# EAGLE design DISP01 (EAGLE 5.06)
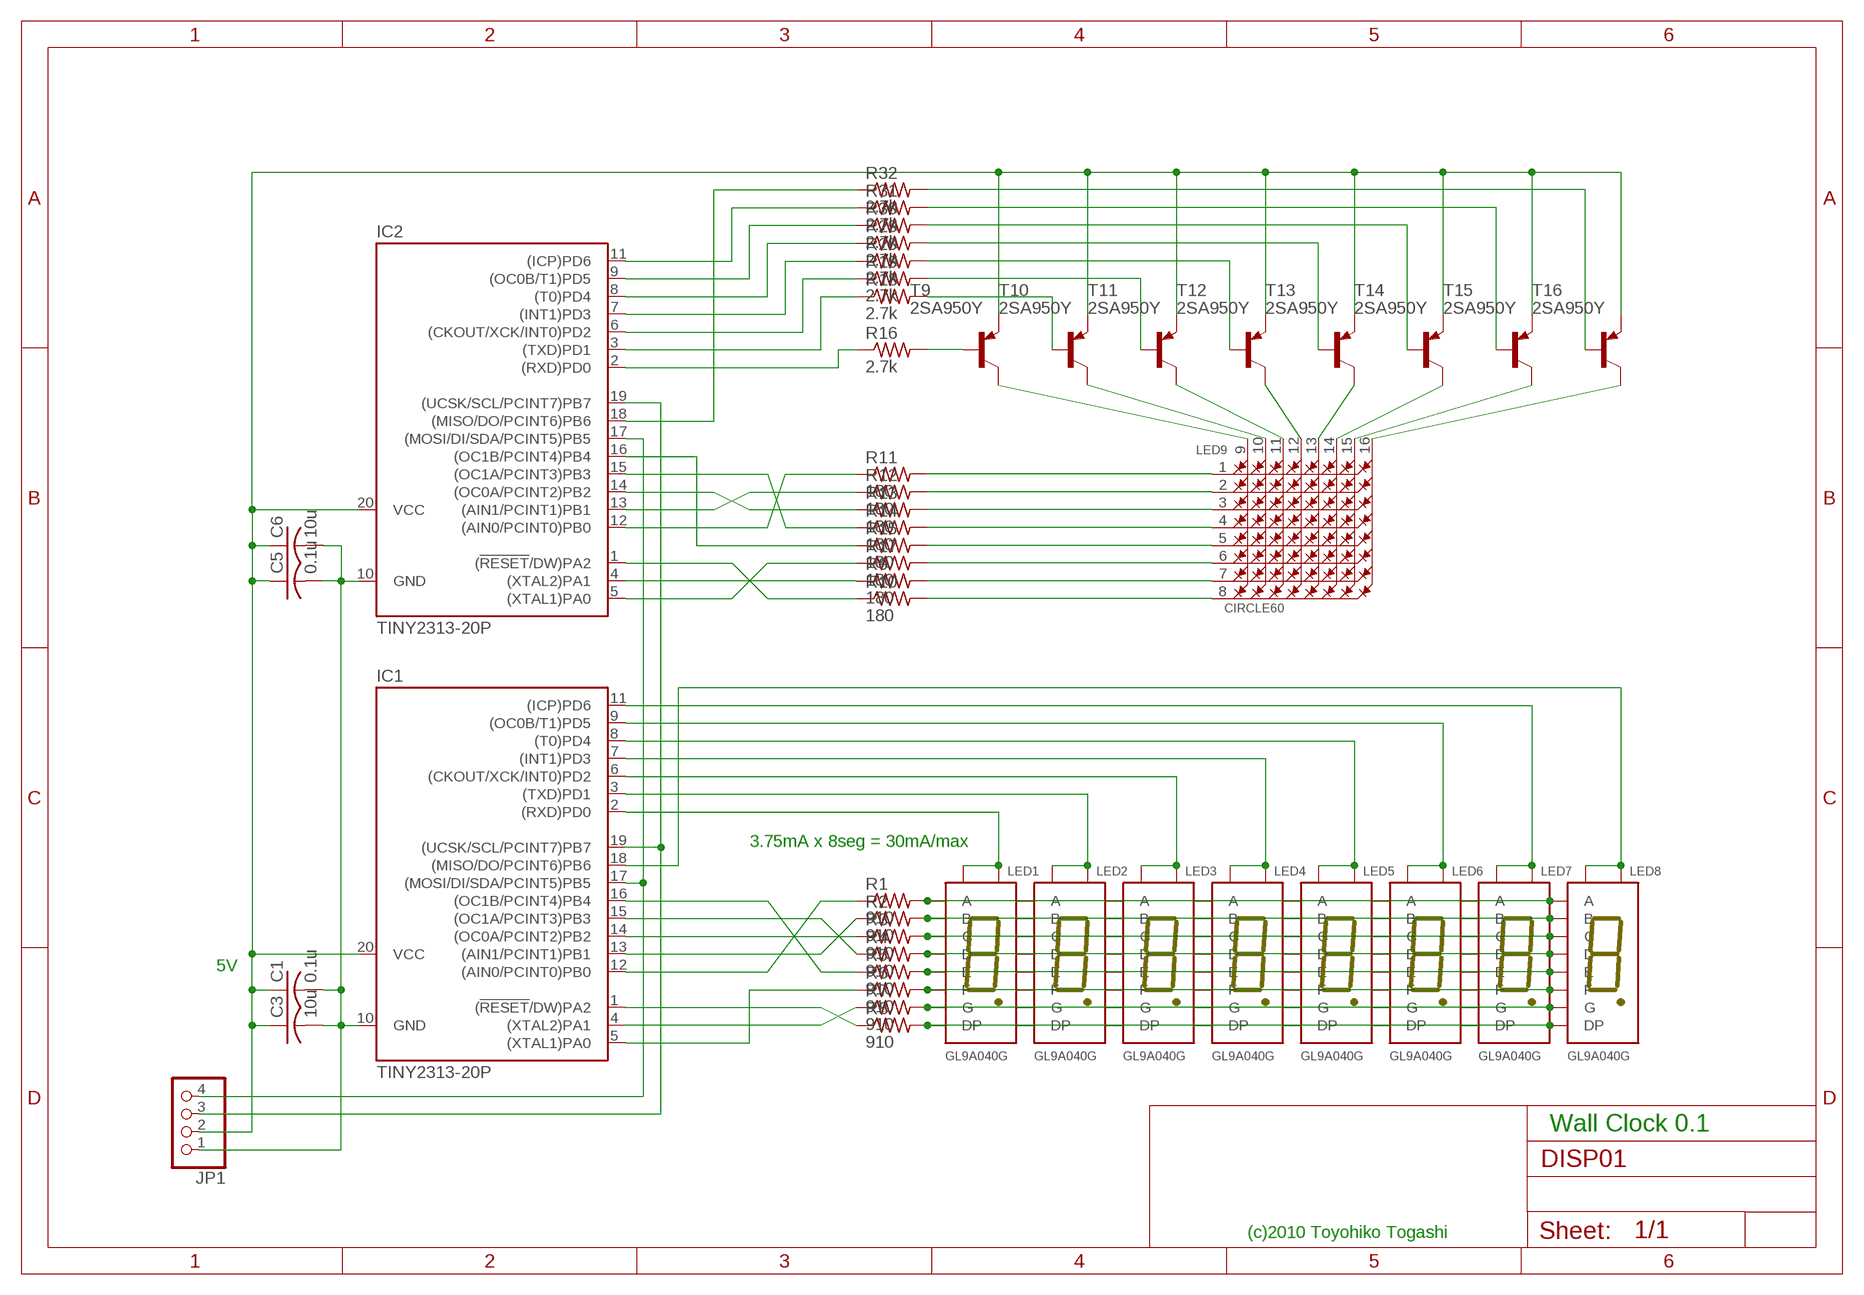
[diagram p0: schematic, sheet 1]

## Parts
C1  0.1u  C-US025-025X050  [C025-025X050]
C3  10u  C-US025-025X050  [C025-025X050]
C5  0.1u  C-US025-025X050  [C025-025X050]
C6  10u  C-US025-025X050  [C025-025X050]
IC1  TINY2313-20P  [DIL20]
IC2  TINY2313-20P  [DIL20]
JP1  PINHD-1X4  [1X04]
LED1  GL9A040G  [GL9A040G]
LED2  GL9A040G  [GL9A040G]
LED3  GL9A040G  [GL9A040G]
LED4  GL9A040G  [GL9A040G]
LED5  GL9A040G  [GL9A040G]
LED6  GL9A040G  [GL9A040G]
LED7  GL9A040G  [GL9A040G]
LED8  GL9A040G  [GL9A040G]
LED9  CIRCLE60  [CIRCLE60]
R1  910  R-US_0204/5  [0204/5]
R2  910  R-US_0204/5  [0204/5]
R3  910  R-US_0204/5  [0204/5]
R4  910  R-US_0204/5  [0204/5]
R5  910  R-US_0204/5  [0204/5]
R6  910  R-US_0204/7  [0204/7]
R7  910  R-US_0204/7  [0204/7]
R8  910  R-US_0204/7  [0204/7]
R9  180  R-US_0204/5  [0204/5]
R10  180  R-US_0204/5  [0204/5]
R11  180  R-US_0204/5  [0204/5]
R12  180  R-US_0204/5  [0204/5]
R13  180  R-US_0204/5  [0204/5]
R14  180  R-US_0204/5  [0204/5]
R15  180  R-US_0204/5  [0204/5]
R16  2.7k  R-US_0204/5  [0204/5]
R17  180  R-US_0204/5  [0204/5]
R18  2.7k  R-US_0204/5  [0204/5]
R19  2.7k  R-US_0204/5  [0204/5]
R20  2.7k  R-US_0204/5  [0204/5]
R29  2.7k  R-US_0204/5  [0204/5]
R30  2.7k  R-US_0204/7  [0204/7]
R31  2.7k  R-US_0204/7  [0204/7]
R32  2.7k  R-US_0204/5  [0204/5]
T9  2SA950Y  -PNP-TO92-ECB  [TO92-ECB]
T10  2SA950Y  -PNP-TO92-ECB  [TO92-ECB]
T11  2SA950Y  -PNP-TO92-ECB  [TO92-ECB]
T12  2SA950Y  -PNP-TO92-ECB  [TO92-ECB]
T13  2SA950Y  -PNP-TO92-ECB  [TO92-ECB]
T14  2SA950Y  -PNP-TO92-ECB  [TO92-ECB]
T15  2SA950Y  -PNP-TO92-ECB  [TO92-ECB]
T16  2SA950Y  -PNP-TO92-ECB  [TO92-ECB]

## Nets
N$1: C1.2 C3.2 C5.2 C6.2 IC1.10(GND) IC2.10(GND) JP1.1
N$2: LED1.P$10(A) LED2.P$10(A) LED3.P$10(A) LED4.P$10(A) LED5.P$10(A) LED6.P$10(A) LED7.P$10(A) LED8.P$10(A) R1.2
N$3: C1.1 C3.1 C5.1 C6.1 IC1.20(VCC) IC2.20(VCC) JP1.2 T9.E T10.E T11.E T12.E T13.E T14.E T15.E T16.E
N$5: IC1.19((UCSK/SCL/PCINT7)PB7) IC2.19((UCSK/SCL/PCINT7)PB7) JP1.3
N$6: LED1.P$9(B) LED2.P$9(B) LED3.P$9(B) LED4.P$9(B) LED5.P$9(B) LED6.P$9(B) LED7.P$9(B) LED8.P$9(B) R2.2
N$7: LED1.P$8(C) LED2.P$8(C) LED3.P$8(C) LED4.P$8(C) LED5.P$8(C) LED6.P$8(C) LED7.P$8(C) LED8.P$8(C) R3.2
N$8: LED1.P$5(D) LED2.P$5(D) LED3.P$5(D) LED4.P$5(D) LED5.P$5(D) LED6.P$5(D) LED7.P$5(D) LED8.P$5(D) R4.2
N$9: LED1.P$4(E) LED2.P$4(E) LED3.P$4(E) LED4.P$4(E) LED5.P$4(E) LED6.P$4(E) LED7.P$4(E) LED8.P$4(E) R5.2
N$10: LED1.P$2(F) LED2.P$2(F) LED3.P$2(F) LED4.P$2(F) LED5.P$2(F) LED6.P$2(F) LED7.P$2(F) LED8.P$2(F) R6.2
N$11: LED1.P$7(DP) LED2.P$7(DP) LED3.P$7(DP) LED4.P$7(DP) LED5.P$7(DP) LED6.P$7(DP) LED7.P$7(DP) LED8.P$7(DP) R8.2
N$12: LED1.P$3(G) LED2.P$3(G) LED3.P$3(G) LED4.P$3(G) LED5.P$3(G) LED6.P$3(G) LED7.P$3(G) LED8.P$3(G) R7.2
N$14: IC1.5((XTAL1)PA0) R6.1
N$15: IC1.4((XTAL2)PA1) R7.1
N$16: IC1.1((!RESET!/DW)PA2) R8.1
N$17: IC1.12((AIN0/PCINT0)PB0) R1.1
N$18: LED9.1(ROW1) R11.2
N$19: IC1.13((AIN1/PCINT1)PB1) R2.1
N$20: IC1.14((OC0A/PCINT2)PB2) R3.1
N$21: IC1.15((OC1A/PCINT3)PB3) R4.1
N$22: IC1.16((OC1B/PCINT4)PB4) R5.1
N$23: LED9.2(ROW2) R12.2
N$24: LED9.3(ROW3) R13.2
N$25: IC1.2((RXD)PD0) LED1.P$1(CA1) LED1.P$6(CA6)
N$26: LED9.4(ROW4) R14.2
N$27: LED9.5(ROW5) R15.2
N$28: IC1.18((MISO/DO/PCINT6)PB6) LED8.P$1(CA1) LED8.P$6(CA6)
N$29: LED9.6(ROW6) R17.2
N$30: LED9.7(ROW7) R9.2
N$31: LED9.8(ROW8) R10.2
N$32: LED9.9(COL1) T9.C
N$34: IC1.17((MOSI/DI/SDA/PCINT5)PB5) IC2.17((MOSI/DI/SDA/PCINT5)PB5) JP1.4
N$35: LED9.10(COL2) T10.C
N$36: R16.2 T9.B
N$37: IC2.5((XTAL1)PA0) R17.1
N$38: IC2.4((XTAL2)PA1) R9.1
N$39: IC2.1((!RESET!/DW)PA2) R10.1
N$40: IC2.12((AIN0/PCINT0)PB0) R11.1
N$41: IC2.13((AIN1/PCINT1)PB1) R12.1
N$42: IC2.14((OC0A/PCINT2)PB2) R13.1
N$43: IC2.15((OC1A/PCINT3)PB3) R14.1
N$44: IC2.16((OC1B/PCINT4)PB4) R15.1
N$45: IC2.2((RXD)PD0) R16.1
N$46: R18.2 T10.B
N$47: R19.2 T11.B
N$48: LED9.11(COL3) T11.C
N$49: R20.2 T12.B
N$50: R29.2 T13.B
N$51: R30.2 T14.B
N$52: R31.2 T15.B
N$53: IC2.3((TXD)PD1) R18.1
N$54: IC2.6((CKOUT/XCK/INT0)PD2) R19.1
N$55: IC2.7((INT1)PD3) R20.1
N$56: IC2.8((T0)PD4) R29.1
N$57: IC2.9((OC0B/T1)PD5) R30.1
N$58: IC2.11((ICP)PD6) R31.1
N$60: LED9.12(COL4) T12.C
N$61: R32.2 T16.B
N$62: IC2.18((MISO/DO/PCINT6)PB6) R32.1
N$63: LED9.13(COL5) T13.C
N$64: LED9.14(COL6) T14.C
N$65: LED9.15(COL7) T15.C
N$66: LED9.16(COL8) T16.C
N$98: IC1.3((TXD)PD1) LED2.P$1(CA1) LED2.P$6(CA6)
N$99: IC1.6((CKOUT/XCK/INT0)PD2) LED3.P$1(CA1) LED3.P$6(CA6)
N$100: IC1.7((INT1)PD3) LED4.P$1(CA1) LED4.P$6(CA6)
N$101: IC1.8((T0)PD4) LED5.P$1(CA1) LED5.P$6(CA6)
N$102: IC1.9((OC0B/T1)PD5) LED6.P$1(CA1) LED6.P$6(CA6)
N$103: IC1.11((ICP)PD6) LED7.P$1(CA1) LED7.P$6(CA6)

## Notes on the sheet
- 3.75mA x 8seg = 30mA/max
- 5V
- Wall Clock 0.1
- (c)2010 Toyohiko Togashi

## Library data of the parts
C1 C3 C5 C6 = rcl:C-US: CAPACITOR, American symbol
IC1 IC2 = TOG:TINY2313: 8-bit AVR Microcontroller with 2K Bytes Flash Source: http://www.atmel.com .. doc2543.pdf
JP1 = pinhead:PINHD-1X4: PIN HEADER
LED1-LED8 = TOG:GL9A040G: 7 Segment LED
LED9 = TOG:CIRCLE60: 60 dot circle line LED 8x8 matrix connection
R1-R20 R29-R32 = rcl:R-US_: RESISTOR, American symbol
T9-T16 = transistor-neu-to92:*-PNP-: PNP Transistror

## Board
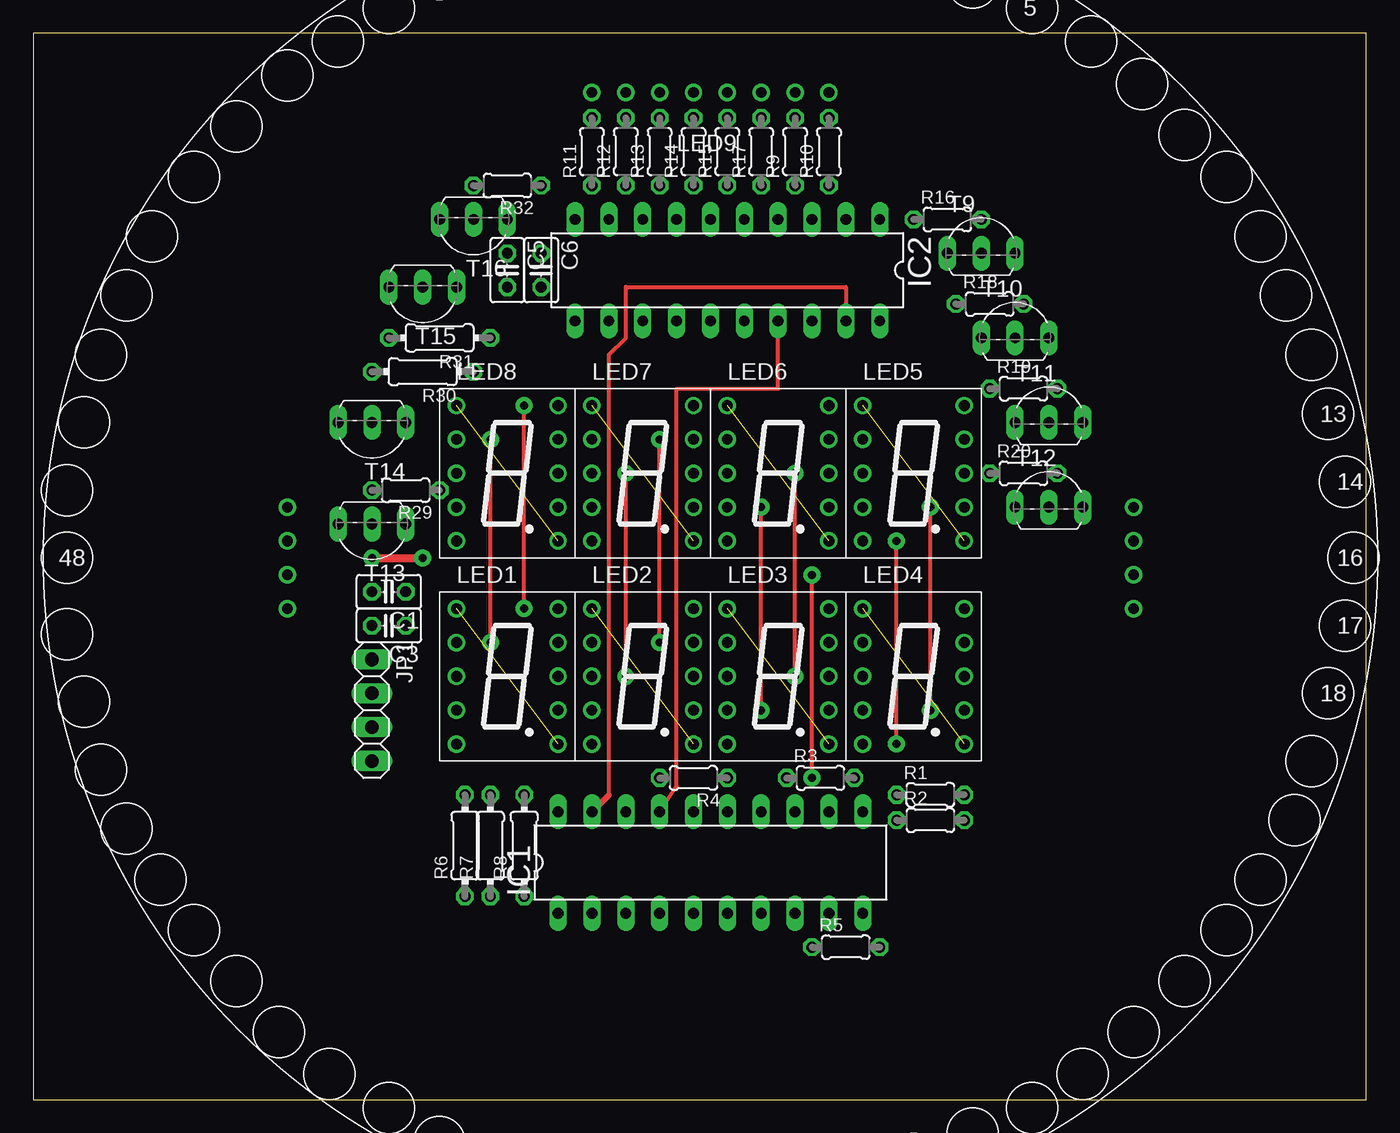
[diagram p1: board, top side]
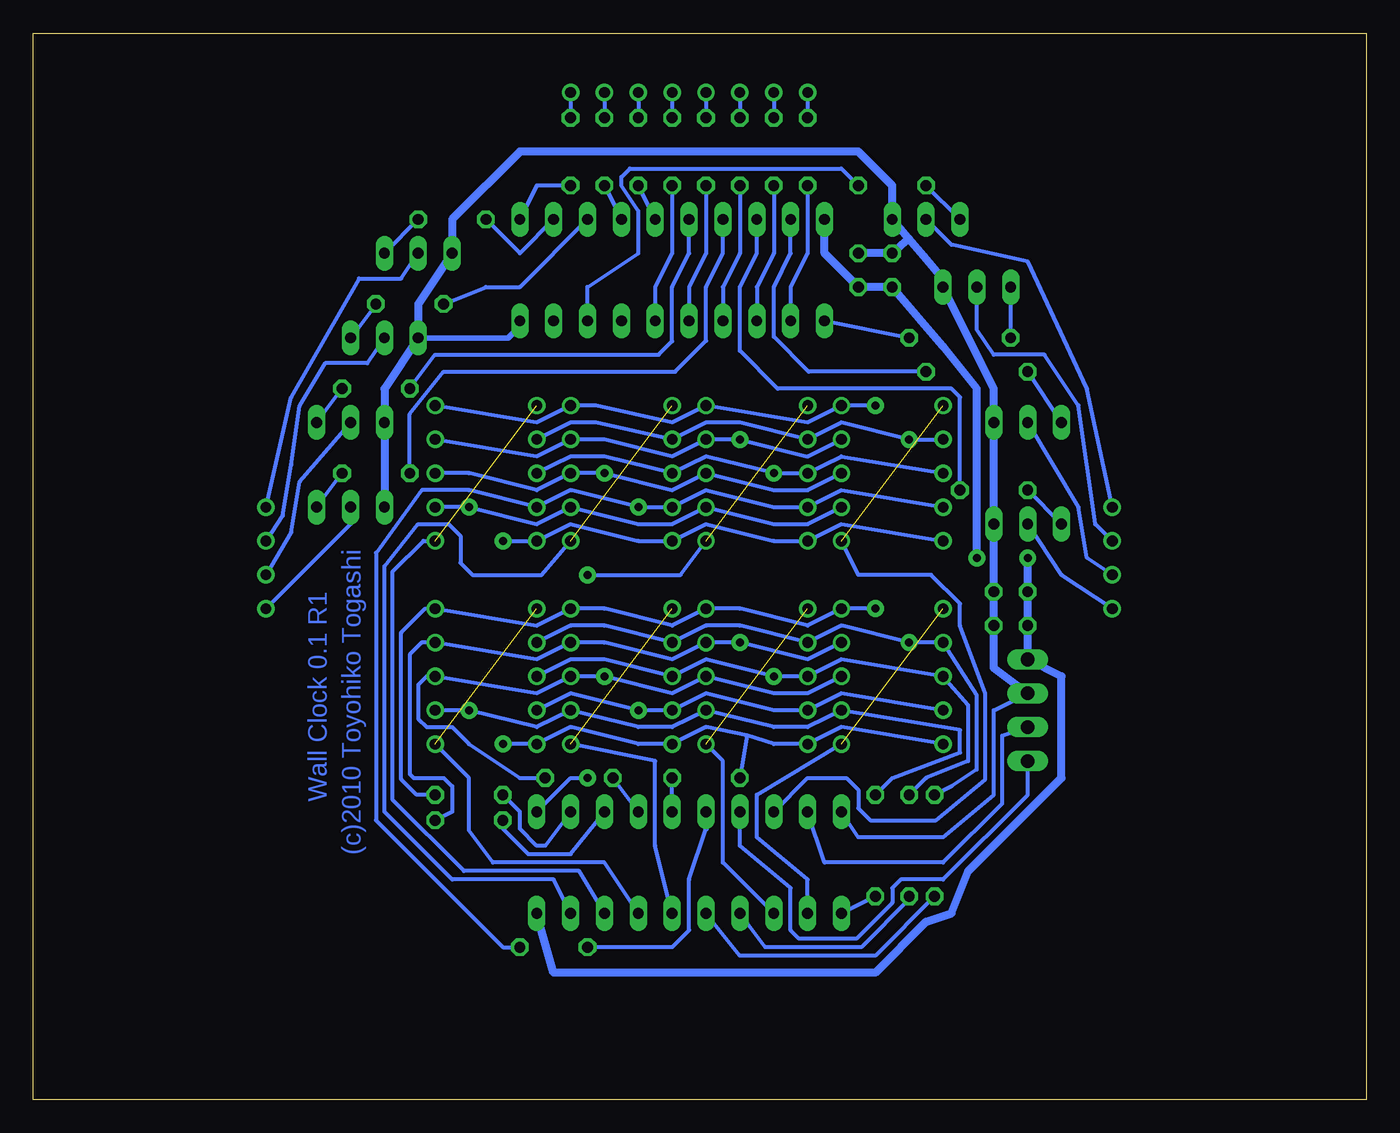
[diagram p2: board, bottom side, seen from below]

Size 100 x 80 mm. Coordinates in mm from the lower left corner, seen from the top.
Outline: 0,0 100,0 100,80 0,80 0,0
Copper layers (1*16): Top 0.035mm / dielectric 1.5mm / Bottom 0.035mm
Design rules "default": minimum track width 10mil, minimum drill 24mil, track to track 8mil, track to pad 8mil, pad to pad 8mil, via to via 8mil, smd to smd 8mil, copper to edge 40mil, drill to drill 8mil, minimum pad ring 10mil, minimum via ring 8mil, stop-mask expansion 4mil, vias tented up to drill 0mil, thermal gap 10mil

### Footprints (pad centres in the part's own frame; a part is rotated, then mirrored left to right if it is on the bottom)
C025-025X050 = drill 0.813 octagon: 1 -1.27,0; 2 1.27,0
DIL20 = drill 0.813 long: 1 -11.43,-3.81; 2 -8.89,-3.81; 3 -6.35,-3.81; 4 -3.81,-3.81; 5 -1.27,-3.81; 6 1.27,-3.81; 7 3.81,-3.81; 8 6.35,-3.81; 9 8.89,-3.81; 10 11.43,-3.81; 11 11.43,3.81; 12 8.89,3.81; 13 6.35,3.81; 14 3.81,3.81; 15 1.27,3.81; 16 -1.27,3.81; 17 -3.81,3.81; 18 -6.35,3.81; 19 -8.89,3.81; 20 -11.43,3.81
1X04 = drill 1.016 long: 1 -3.81,0; 2 -1.27,0; 3 1.27,0; 4 3.81,0
GL9A040G = drill 0.8 round: P$1 -3.81,5.08; P$2 -3.81,2.54; P$3 -3.81,0; P$4 -3.81,-2.54; P$5 -3.81,-5.08; P$6 3.81,-5.08; P$7 3.81,-2.54; P$8 3.81,0; P$9 3.81,2.54; P$10 3.81,5.08
CIRCLE60 = drill 0.8 round: 1 -8.89,34.925; 2 -6.35,34.925; 3 -3.81,34.925; 4 -1.27,34.925; 5 1.27,34.925; 6 3.81,34.925; 7 6.35,34.925; 8 8.89,34.925; 9 31.75,3.81; 10 31.75,1.27; 11 31.75,-1.27; 12 31.75,-3.81; 13 -31.75,-3.81; 14 -31.75,-1.27; 15 -31.75,1.27; 16 -31.75,3.81
0204/5 = drill 0.813 octagon: 1 -2.54,0; 2 2.54,0
0204/7 = drill 0.813 octagon: 1 -3.81,0; 2 3.81,0
TO92-ECB = drill 0.813 long: B 2.54,0; C 0,0; E -2.54,0

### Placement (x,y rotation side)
C1  26.67,38.1 180 top
C3  26.67,35.56 180 top
C5  35.56,62.23 270 top
C6  38.1,62.23 270 top
IC1  50.8,17.78 0 top
IC2  52.07,62.23 180 top
JP1  25.4,29.21 270 top
LED1  35.56,31.75 0 top
LED2  45.72,31.75 0 top
LED3  55.88,31.75 0 top
LED4  66.04,31.75 0 top
LED5  66.04,46.99 0 top
LED6  55.88,46.99 0 top
LED7  45.72,46.99 0 top
LED8  35.56,46.99 0 top
LED9  50.8,40.64 0 top
R1  67.31,22.86 0 top
R2  67.31,20.95 0 top
R3  59.05,24.13 0 top
R4  49.53,24.13 180 top
R5  60.96,11.43 0 top
R6  32.38,19.05 90 top
R7  34.29,19.05 90 top
R8  36.83,19.05 90 top
R9  57.15,71.12 90 top
R10  59.69,71.12 90 top
R11  41.91,71.12 90 top
R12  44.45,71.12 90 top
R13  46.99,71.12 90 top
R14  49.53,71.12 90 top
R15  52.07,71.12 90 top
R16  68.58,66.04 0 top
R17  54.61,71.12 90 top
R18  71.75,59.69 0 top
R19  74.3,53.34 0 top
R20  74.3,46.99 0 top
R29  27.94,45.72 180 top
R30  29.21,54.61 180 top
R31  30.48,57.15 180 top
R32  35.56,68.58 180 top
T9  71.12,63.5 0 top
T10  73.66,57.15 0 top
T11  76.2,50.8 0 top
T12  76.2,44.45 0 top
T13  25.4,43.18 180 top
T14  25.4,50.8 180 top
T15  29.21,60.96 180 top
T16  33.02,66.04 180 top

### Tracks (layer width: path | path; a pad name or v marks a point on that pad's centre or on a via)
N$1  (via drill 0.6 pad 1.27)
  Top 0.61: v25.4,40.64 v29.21,40.64
  Bottom 0.61: IC1.10 60.96,9.53 36.83,9.53 33.02,13.34 31.11,13.97 29.84,17.14 22.86,24.13 22.86,31.75 JP1.1 C3.2 C1.2 v25.4,40.64 | v29.21,40.64 29.21,53.34 31.75,56.52 C5.2 C6.2 40.64,63.5 IC2.10
N$2  (via drill 0.6 pad 1.27)
  Top 0.305: v36.83,36.83 v36.83,52.07
  Bottom 0.305: v36.83,52.07 LED8.P$10 41.91,50.8 LED7.P$10 52.07,50.8 57.78,52.07 LED6.P$10 62.23,50.8 LED5.P$10 | v36.83,36.83 LED1.P$10 41.91,35.56 46.99,36.83 LED2.P$10 52.07,35.56 57.15,36.83 LED3.P$10 62.23,35.56 LED4.P$10 70.59,36.83 72.39,35.03 72.39,24.02 71.23,22.86 R1.2
N$3
  Bottom 0.305: 34.3,64.59 34.34,64.64 | JP1.2 27.94,29.21 27.94,22.86 31.75,19.68 38.1,19.68 IC1.20
  Bottom 0.406: T10.E 64.4,57.15 63.5,58.05 IC2.20
  Bottom 0.61: T12.E T11.E 73.66,53.34 T10.E 71.12,59.69 T9.E 68.58,66.04 63.5,71.12 38.1,71.12 35.56,68.58 T16.E 34.34,64.64 | JP1.2 27.94,32.38 C3.1 C1.1 T13.E T14.E 27.94,53.34 T15.E 31.75,61.59 33.16,63.27 34.3,64.59 C5.1 C6.1
N$5
  Top 0.305: 43.18,22.86 43.18,55.88 44.45,57.15 44.45,60.96 60.96,60.96 IC2.19
  Top 0.406: IC1.19 43.18,22.86
  Bottom 0.305: JP1.3 27.3,27.3 27.3,22.23 31.75,17.78 40.64,17.78 IC1.19
N$6  (via drill 0.6 pad 1.27)
  Top 0.305: v46.99,34.29 v46.99,49.53
  Bottom 0.305: LED8.P$9 41.91,48.26 v46.99,49.53 LED7.P$9 52.07,48.26 57.15,49.53 LED6.P$9 62.23,48.26 LED5.P$9 | LED1.P$9 41.91,33.02 v46.99,34.29 LED2.P$9 52.07,33.02 57.15,34.29 LED3.P$9 62.23,33.02 LED4.P$9 70.86,34.29 71.75,33.39 71.75,24.43 71.45,24.13 69.22,24.13 68.58,23.5 68.58,21.59 R2.2
N$7  (via drill 0.6 pad 1.27)
  Top 0.305: v57.15,31.75 v57.15,46.99
  Bottom 0.305: LED8.P$8 41.91,45.72 44.45,45.72 LED7.P$8 52.07,45.72 v57.15,46.99 LED6.P$8 62.23,45.72 67.31,46.99 LED5.P$8 | LED1.P$8 41.91,30.48 44.45,30.48 LED2.P$8 52.07,30.48 v57.15,31.75 LED3.P$8 62.23,30.48 LED4.P$8 70.48,31.75 71.12,31.11 71.12,28.57 70.48,27.94 68.58,27.94 67.31,26.67 63.5,24.13 R3.2
N$8  (via drill 0.6 pad 1.27)
  Top 0.305: v64.77,26.67 v64.77,41.91
  Bottom 0.305: v64.77,26.67 LED4.P$5 59.69,27.94 54.61,26.67 LED3.P$5 49.53,27.94 46.46,27.32 | v64.77,41.91 LED5.P$5 59.69,43.18 54.61,41.91 LED6.P$5 49.53,43.18 44.45,41.91 LED7.P$5 39.37,43.18 LED8.P$5 | 46.46,27.32 44.45,26.67 LED2.P$5 39.37,27.94 LED1.P$5 | 46.46,27.32 R4.2
N$9  (via drill 0.6 pad 1.27)
  Top 0.305: v54.61,29.21 v54.61,44.45
  Bottom 0.305: LED8.P$4 39.37,45.72 LED7.P$4 44.45,44.45 49.53,45.72 LED6.P$4 v54.61,44.45 59.69,45.72 LED5.P$4 67.31,45.72 70.86,45.72 74.3,41.02 74.3,20.95 64.77,11.43 R5.2 | LED1.P$4 39.37,30.48 LED2.P$4 44.45,29.21 49.53,30.48 LED3.P$4 v54.61,29.21 59.69,30.48 LED4.P$4
N$10  (via drill 0.6 pad 1.27)
  Top 0.305: v34.29,34.29 v34.29,49.53
  Bottom 0.305: LED8.P$2 v34.29,49.53 39.37,50.8 LED7.P$2 46.99,50.8 49.53,50.8 LED6.P$2 57.78,50.8 59.69,50.8 LED5.P$2 | LED4.P$2 59.69,35.56 57.15,35.56 LED3.P$2 49.53,35.56 46.99,35.56 LED2.P$2 39.37,35.56 v34.29,34.29 LED1.P$2 29.21,30.33 29.21,24.77 31.11,23.5 R6.2
N$11  (via drill 0.6 pad 1.27)
  Top 0.305: v67.31,29.21 v67.31,44.45
  Bottom 0.305: LED4.P$7 v67.31,29.21 62.23,27.94 LED3.P$7 54.61,27.94 52.07,27.94 LED2.P$7 44.45,27.94 41.91,27.94 LED1.P$7 30.48,27.73 30.48,26.04 35.56,24.13 R8.2 | LED5.P$7 v67.31,44.45 62.23,43.18 LED6.P$7 54.61,43.18 52.07,43.18 LED7.P$7 44.45,43.18 41.91,43.18 LED8.P$7
N$12  (via drill 0.6 pad 1.27)
  Top 0.305: v44.45,31.75 v44.45,46.99
  Bottom 0.305: LED8.P$3 39.37,48.26 LED7.P$3 v44.45,46.99 49.53,48.26 LED6.P$3 57.15,48.26 59.69,48.26 LED5.P$3 | LED4.P$3 59.69,33.02 57.15,33.02 LED3.P$3 49.53,33.02 v44.45,31.75 LED2.P$3 39.37,33.02 LED1.P$3 29.84,29.58 29.84,25.4 33.02,24.13 R7.2
N$14
  Bottom 0.305: R6.1 36.83,10.79 46.99,10.79 IC1.5
N$15
  Bottom 0.305: R7.1 34.29,15.02 37.88,11.43 45.09,11.43 IC1.4
N$16
  Bottom 0.305: R8.1 IC1.1
N$17
  Bottom 0.305: IC1.12 61.59,19.05 62.23,19.05 63.5,20.32 63.5,21.59 R1.1
N$18
  Bottom 0.305: LED9.1 R11.2
N$19
  Bottom 0.305: R2.1 64.77,20.32 62.87,18.41 59.69,18.41 IC1.13
N$20
  Bottom 0.305: IC1.14 R3.1
N$21
  Bottom 0.305: IC1.15 R4.1
N$22
  Bottom 0.305: 49.53,20.32 50.8,16.51 50.8,12.7 52.07,11.43 R5.1
  Bottom 0.406: 49.53,20.32 IC1.16
N$23
  Bottom 0.305: LED9.2 R12.2
N$24
  Bottom 0.305: LED9.3 R13.2
N$25  (1 unrouted)
  Bottom 0.305: IC1.2 41.91,16.51 45.72,19.68 45.72,22.86 LED1.P$6
N$26
  Bottom 0.305: LED9.4 R14.2
N$27
  Bottom 0.305: LED9.5 R15.2
N$28  (1 unrouted)
  Bottom 0.305: IC1.18 41.91,24.13 39,24.13 38.1,23.23 38.1,21.85 37.2,20.95 32.28,20.95 28.57,24.02 28.57,30.48 30.48,35.56 30.48,37.21 32.64,39.37 38.1,39.37 LED8.P$6
N$29
  Bottom 0.305: LED9.6 R17.2
N$30
  Bottom 0.305: LED9.7 R9.2
N$31
  Bottom 0.305: LED9.8 R10.2
N$32
  Bottom 0.305: LED9.9 80.64,52.7 75.56,61.59 72.39,61.59 T9.C
N$34
  Top 0.305: IC1.17 48.26,23.5 48.26,53.34 55.88,53.34 IC2.17
  Bottom 0.305: JP1.4 25.4,22.86 31.75,16.51 34.92,16.51 35.56,15.88 35.56,14.76 38.25,12.06 42.55,12.06 43.18,12.7 43.18,15.88 46.99,19.05 IC1.17
N$35
  Bottom 0.305: LED9.10 81.28,43.81 80.64,47.62 80.01,52.07 78.11,55.24 74.93,55.24 T10.C
N$36
  Bottom 0.305: R16.2 T9.B
N$37
  Bottom 0.305: IC2.5 R17.1
N$38
  Bottom 0.305: R9.1 IC2.4
N$39
  Bottom 0.305: R10.1 62.23,68.58 IC2.1
N$40
  Bottom 0.305: R11.1 41.91,63.5 43.18,60.96 IC2.12
N$41
  Bottom 0.305: R12.1 44.45,63.5 45.72,60.96 IC2.13
N$42
  Bottom 0.305: R13.1 46.99,63.5 48.26,60.96 IC2.14
N$43
  Bottom 0.305: R14.1 49.53,63.5 50.8,60.96 IC2.15
N$44
  Bottom 0.305: R15.1 52.07,63.5 53.34,60.96 IC2.16
N$45
  Bottom 0.305: IC2.2 63.5,63.5 R16.1
N$46
  Bottom 0.305: R18.2 T10.B
N$47
  Bottom 0.305: T11.B R19.2
N$48
  Bottom 0.305: LED9.11 80.64,42.55 80.01,46.35 T11.C
N$49
  Bottom 0.305: T12.B R20.2
N$50
  Bottom 0.305: T13.B R29.2
N$51
  Bottom 0.305: T14.B R30.2
N$52
  Bottom 0.305: R31.2 T15.B
N$53
  Bottom 0.305: R18.1 66.04,60.96 63.5,60.96 IC2.3
N$54
  Bottom 0.305: R19.1 69.85,55.88 53.09,55.88 52.07,56.9 52.07,60.96 50.8,63.5 IC2.6
N$55
  Bottom 0.305: R20.1 71.75,51.44 69.22,54.61 51.85,54.61 49.53,56.93 49.53,60.96 48.26,63.5 IC2.7
N$56
  Bottom 0.305: R29.1 30.48,52.7 31.11,53.34 44.15,53.34 46.99,56.18 46.99,60.96 45.72,63.5 IC2.8
N$57
  Bottom 0.305: R30.1 41.83,54.61 44.45,57.23 44.45,60.96 43.18,63.5 IC2.9
N$58
  Bottom 0.305: R31.1 IC2.11
N$60
  Bottom 0.305: T12.C 76.2,43.18 LED9.12
N$61
  Bottom 0.305: T16.B R32.2
N$62
  Bottom 0.305: IC2.18 58.42,60.96 54.61,63.5 54.61,66.67 55.88,68.58 55.88,69.22 55.24,69.85 39.37,69.85 R32.1
N$63
  Bottom 0.305: LED9.13 22.86,39.37 T13.C
N$64
  Bottom 0.305: LED9.14 20.95,40.64 21.59,44.45 T14.C
N$65
  Bottom 0.305: LED9.15 20.32,43.18 21.59,52.07 24.13,55.88 27.94,55.88 29.21,57.78 T15.C
N$66
  Bottom 0.305: T16.C 31.11,64.14 25.4,62.87 20.95,53.34 LED9.16
N$98  (1 unrouted)
  Bottom 0.305: IC1.3 48.26,17.78 48.26,25.4 LED2.P$6
N$99  (1 unrouted)
  Bottom 0.305: IC1.6 53.34,19.05 53.34,25.4 LED3.P$6
N$100  (1 unrouted)
  Bottom 0.305: IC1.7 57.15,17.78 65.51,17.78 67.31,20.21 67.31,24.13 LED4.P$6
N$101  (1 unrouted)
  Bottom 0.305: IC1.8 59.05,17.14 67.69,17.14 73.03,22.48 73.03,39.62 70.74,41.91 LED5.P$6
N$102  (1 unrouted)
  Bottom 0.305: IC1.9 60.96,16.51 68.58,16.51 73.66,21.59 73.66,40.01 71.12,43.18 68.84,43.18 67.94,42.28 67.94,40.27 67.05,39.37 61.86,39.37 LED6.P$6
N$103  (via drill 0.6 pad 1.27)  (1 unrouted)
  Top 0.305: v58.42,24.13 v58.42,39.37
  Bottom 0.305: IC1.11 59.69,24.13 v58.42,24.13 | v58.42,39.37 51.44,39.37 LED7.P$6

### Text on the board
Bottom: (c)2010 Toyohiko Togashi | Wall Clock 0.1 R1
